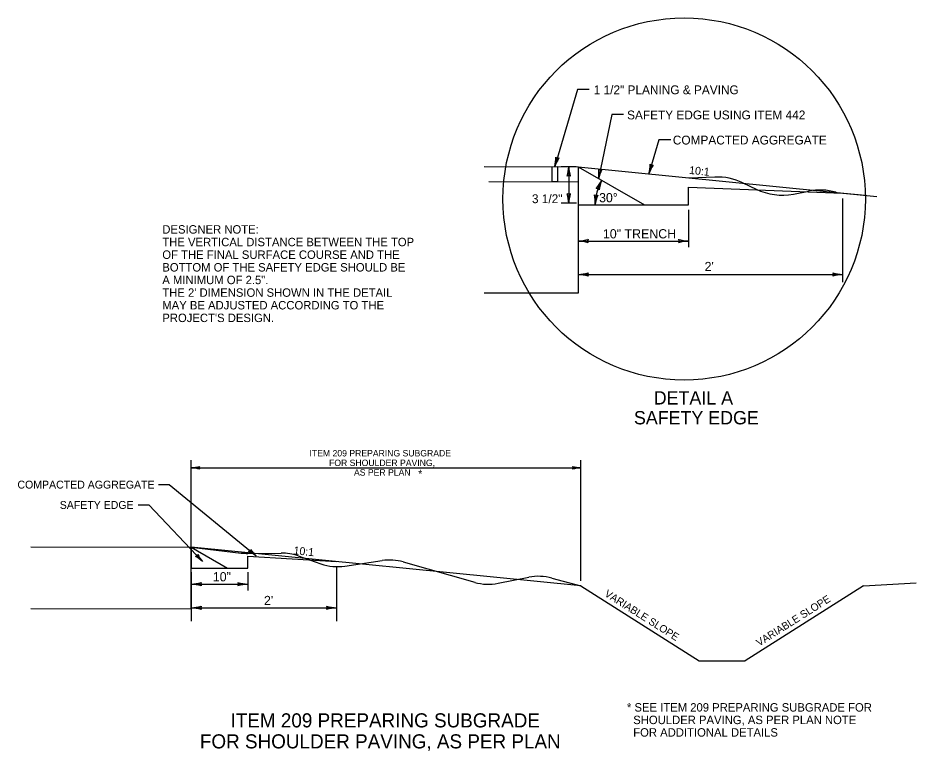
# Model space of a CAD drawing. Extents: x 12069 to 12219, y 28137 to 28231.
# Drawn here: x 12204.37 to 12219.29, y 28184.37 to 28196.55 of the extents above; entities that cross this region are included whole.
import ezdxf

# ---------------------------------------------------------------- set-up
doc = ezdxf.new("R2010")
doc.units = 0
doc.layers.add('Default', color=7, linetype='Continuous')
doc.layers.add('SH_Data', color=7, linetype='Continuous')

msp = doc.modelspace()

# ---------------------------------------------------------------- linework, layer by layer
at = {"layer": 'Default'}
for p, q in [((12213.665, 28195.359), (12213.289, 28194.077)), ((12213.862, 28195.359), (12213.665, 28195.359)), ((12214.236, 28194.941), (12214.017, 28193.874)), ((12214.433, 28194.941), (12214.236, 28194.941)), ((12215.019, 28194.524), (12214.854, 28193.958)), ((12215.217, 28194.524), (12215.019, 28194.524)), ((12213.679, 28194.076), (12213.679, 28193.47)), ((12213.679, 28194.076), (12214.777, 28193.442)), ((12213.679, 28194.076), (12218.639, 28193.578)), ((12213.679, 28193.86), (12213.679, 28193.813)), ((12213.679, 28193.86), (12213.679, 28191.976)), ((12215.519, 28193.891), (12215.95, 28193.905)), ((12216.411, 28193.808), (12216.634, 28193.701)), ((12215.509, 28193.442), (12215.509, 28193.733)), ((12217.252, 28193.622), (12217.506, 28193.67)), ((12213.679, 28193.442), (12214.777, 28193.442)), ((12214.777, 28193.442), (12215.509, 28193.442)), ((12213.679, 28191.976), (12212.119, 28191.976)), ((12206.71, 28188.797), (12206.886, 28188.797)), ((12206.886, 28188.797), (12208.33, 28187.608)), ((12206.371, 28188.459), (12206.547, 28188.459)), ((12206.547, 28188.459), (12207.439, 28187.515)), ((12213.721, 28187.108), (12207.253, 28187.755)), ((12207.253, 28187.755), (12208.083, 28187.656)), ((12208.19, 28187.65), (12208.744, 28187.655)), ((12208.192, 28187.603), (12209.666, 28187.513)), ((12209.027, 28187.609), (12209.406, 28187.476)), ((12209.804, 28187.438), (12210.421, 28187.53)), ((12210.773, 28187.507), (12211.96, 28187.169)), ((12212.35, 28187.153), (12212.859, 28187.254)), ((12213.241, 28187.24), (12213.721, 28187.108))]:
    msp.add_line(p, q, dxfattribs=at)
for points in [[(12217.957, 28193.653), (12217.976, 28193.648), (12218.446, 28193.6)], [(12214.777, 28193.442), (12215.509, 28193.442), (12215.509, 28193.48)]]:
    msp.add_lwpolyline(points, dxfattribs=at)
msp.add_circle((12215.438, 28193.539), 3.009, dxfattribs=at)
for centre, radius, start, end in [((12214.777, 28193.442), 0.817, 150, 180), ((12215.981, 28192.905), 1, 64.5327, 91.7689), ((12217.064, 28194.604), 1, 244.5327, 280.8088), ((12217.693, 28192.688), 1, 74.7222, 100.8088), ((12208.182, 28188.483), 0.833, 263.2067, 270.5549), ((12208.752, 28186.822), 0.833, 70.7156, 90.5549), ((12210.544, 28186.706), 0.833, 74.0884, 98.4697), ((12209.681, 28188.263), 0.833, 250.7156, 278.4697), ((12213.021, 28186.436), 0.833, 74.6316, 101.2096), ((12212.188, 28187.97), 0.833, 254.0884, 281.2096)]:
    msp.add_arc(centre, radius, start, end, dxfattribs=at)
at = {"layer": 'SH_Data'}
for p, q in [((12213.308, 28194.235), (12213.331, 28194.219)), ((12213.331, 28194.219), (12213.359, 28194.22)), ((12214.873, 28194.117), (12214.896, 28194.101)), ((12214.896, 28194.101), (12214.923, 28194.102)), ((12212.119, 28194.078), (12213.679, 28194.076)), ((12213.246, 28194.076), (12213.333, 28194.077)), ((12213.246, 28193.827), (12213.246, 28194.076)), ((12213.333, 28194.077), (12213.333, 28193.826)), ((12213.646, 28194.076), (12213.396, 28194.076)), ((12213.522, 28194.076), (12213.522, 28193.47)), ((12214.02, 28194.034), (12214.044, 28194.021)), ((12214.044, 28194.021), (12214.072, 28194.024)), ((12212.193, 28193.828), (12213.679, 28193.826)), ((12213.333, 28193.826), (12213.246, 28193.827)), ((12213.522, 28193.927), (12213.496, 28193.918)), ((12213.548, 28193.918), (12213.522, 28193.927)), ((12214.005, 28193.709), (12213.976, 28193.712)), ((12214.026, 28193.689), (12214.005, 28193.709)), ((12215.511, 28193.733), (12218.07, 28193.637)), ((12213.522, 28193.618), (12213.496, 28193.627)), ((12213.548, 28193.627), (12213.522, 28193.618)), ((12213.947, 28193.609), (12213.974, 28193.597)), ((12213.974, 28193.597), (12214.002, 28193.604)), ((12218.07, 28193.546), (12218.07, 28192.156)), ((12213.648, 28193.47), (12213.396, 28193.47)), ((12213.679, 28193.388), (12213.679, 28192.337)), ((12215.509, 28193.357), (12215.509, 28192.737)), ((12213.679, 28192.841), (12215.508, 28192.841)), ((12213.844, 28192.869), (12213.835, 28192.841)), ((12213.835, 28192.841), (12213.844, 28192.814)), ((12215.343, 28192.869), (12215.352, 28192.841)), ((12215.352, 28192.841), (12215.343, 28192.814)), ((12213.844, 28192.311), (12213.835, 28192.284)), ((12217.905, 28192.311), (12217.914, 28192.284)), ((12213.679, 28192.284), (12218.07, 28192.284)), ((12213.835, 28192.284), (12213.844, 28192.257)), ((12217.914, 28192.284), (12217.905, 28192.257)), ((12207.253, 28187.828), (12207.253, 28189.197)), ((12213.721, 28187.194), (12213.721, 28189.197)), ((12207.253, 28189.072), (12213.721, 28189.072)), ((12207.386, 28189.072), (12207.394, 28189.095)), ((12207.394, 28189.048), (12207.386, 28189.072)), ((12213.581, 28189.095), (12213.589, 28189.072)), ((12213.589, 28189.072), (12213.581, 28189.048)), ((12207.253, 28187.755), (12207.253, 28187.901)), ((12204.59, 28187.759), (12207.253, 28187.755)), ((12207.253, 28187.755), (12207.857, 28187.406)), ((12207.253, 28187.755), (12207.253, 28187.406)), ((12207.253, 28187.755), (12207.253, 28187.604)), ((12207.253, 28186.731), (12207.253, 28187.755)), ((12208.206, 28187.679), (12208.227, 28187.692)), ((12208.227, 28187.692), (12208.236, 28187.715)), ((12207.326, 28187.601), (12207.348, 28187.611)), ((12207.348, 28187.611), (12207.36, 28187.633)), ((12208.192, 28187.406), (12208.192, 28187.603)), ((12207.253, 28187.406), (12207.857, 28187.406)), ((12207.857, 28187.406), (12208.192, 28187.406)), ((12209.666, 28187.414), (12209.666, 28186.524)), ((12207.253, 28187.338), (12207.253, 28186.524)), ((12208.192, 28187.338), (12208.192, 28187.034)), ((12207.253, 28187.139), (12208.192, 28187.139)), ((12207.418, 28187.166), (12207.409, 28187.139)), ((12207.409, 28187.139), (12207.418, 28187.112)), ((12208.027, 28187.166), (12208.036, 28187.139)), ((12208.036, 28187.139), (12208.027, 28187.112)), ((12213.721, 28187.108), (12215.689, 28185.862)), ((12218.417, 28187.108), (12216.45, 28185.862)), ((12218.417, 28187.108), (12219.289, 28187.161)), ((12204.588, 28186.735), (12207.253, 28186.731)), ((12207.253, 28186.745), (12209.666, 28186.745)), ((12207.418, 28186.772), (12207.409, 28186.745)), ((12207.409, 28186.745), (12207.418, 28186.717)), ((12209.501, 28186.772), (12209.51, 28186.745)), ((12209.51, 28186.745), (12209.501, 28186.717)), ((12215.689, 28185.862), (12216.45, 28185.862))]:
    msp.add_line(p, q, dxfattribs=at)
for centre, radius, start, end in [((12212.568, 28194.244), 0.741, 346.9376, 359.3148), ((12213.987, 28193.828), 0.741, 148.0129, 160.3902), ((12214.132, 28194.126), 0.741, 346.9376, 359.3148), ((12215.551, 28193.71), 0.741, 148.0129, 160.3902), ((12212.782, 28194.118), 0.741, 344.3491, 356.7263), ((12214.261, 28194.118), 0.741, 183.2737, 195.6509), ((12213.282, 28193.97), 0.741, 352.579, 4.9562), ((12214.735, 28193.696), 0.741, 153.6543, 166.0316), ((12213.385, 28194.212), 0.774, 319.8379, 332.2151), ((12214.791, 28193.57), 0.774, 158.7625, 171.1398), ((12212.782, 28193.427), 0.741, 3.2737, 15.6509), ((12214.261, 28193.427), 0.741, 164.3491, 176.7263), ((12213.186, 28193.467), 0.774, 358.1803, 10.5575), ((12214.726, 28193.33), 0.774, 159.2557, 171.6329), ((12213.635, 28193.614), 0.774, 273.2737, 285.6509), ((12213.635, 28192.068), 0.774, 74.3491, 86.7263), ((12215.552, 28193.614), 0.774, 254.3491, 266.7263), ((12215.552, 28192.068), 0.774, 93.2737, 105.6509), ((12213.635, 28193.057), 0.774, 273.2737, 285.6509), ((12218.114, 28193.057), 0.774, 254.3491, 266.7263), ((12213.635, 28191.511), 0.774, 74.3491, 86.7263), ((12218.114, 28191.511), 0.774, 93.2737, 105.6509), ((12207.216, 28189.731), 0.66, 273.2737, 285.6509), ((12207.216, 28188.413), 0.66, 74.3491, 86.7263), ((12213.759, 28189.731), 0.66, 254.3491, 266.7263), ((12213.759, 28188.413), 0.66, 93.2737, 105.6509), ((12207.94, 28187.075), 0.66, 53.7955, 66.1727), ((12208.778, 28188.092), 0.66, 214.8709, 227.2481), ((12206.986, 28187.035), 0.66, 46.642, 59.0193), ((12207.944, 28187.94), 0.66, 207.7174, 220.0946), ((12207.209, 28187.912), 0.774, 273.2737, 285.6509), ((12207.209, 28186.366), 0.774, 74.3491, 86.7263), ((12208.236, 28187.912), 0.774, 254.3491, 266.7263), ((12208.236, 28186.366), 0.774, 93.2737, 105.6509), ((12207.209, 28187.518), 0.774, 273.2737, 285.6509), ((12207.209, 28185.972), 0.774, 74.3491, 86.7263), ((12209.71, 28187.518), 0.774, 254.3491, 266.7263), ((12209.71, 28185.972), 0.774, 93.2737, 105.6509)]:
    msp.add_arc(centre, radius, start, end, dxfattribs=at)

# ---------------------------------------------------------------- texts
at = {"layer": 'Default'}
for p in [(12215.516, 28193.957), (12208.947, 28187.636)]:
    msp.add_text('10:1', height=0.131, rotation=354.2894, dxfattribs=at).set_placement(p)
at = {"layer": 'SH_Data'}
for s, height, p in [('1 1/2" PLANING & PAVING', 0.147, (12213.936, 28195.28)), ('SAFETY EDGE USING ITEM 442', 0.147, (12214.49, 28194.862)), ('COMPACTED AGGREGATE', 0.147, (12215.25, 28194.445)), ('30%%D', 0.1524, (12214.026, 28193.485)), ('3 1/2"', 0.147, (12212.91, 28193.47)), ('DESIGNER NOTE:', 0.14, (12206.772, 28192.964)), ('10" TRENCH', 0.1537, (12214.089, 28192.884)), ('THE VERTICAL DISTANCE BETWEEN THE TOP', 0.14, (12206.772, 28192.754)), ('OF THE FINAL SURFACE COURSE AND THE', 0.14, (12206.772, 28192.544)), ('BOTTOM OF THE SAFETY EDGE SHOULD BE', 0.14, (12206.772, 28192.334)), ("2'", 0.1537, (12215.777, 28192.34)), ('A MINIMUM OF 2.5".', 0.14, (12206.772, 28192.124)), ("THE 2' DIMENSION SHOWN IN THE DETAIL", 0.14, (12206.772, 28191.914)), ('MAY BE ADJUSTED ACCORDING TO THE ', 0.14, (12206.772, 28191.704)), ("PROJECT'S DESIGN.", 0.14, (12206.772, 28191.494)), ('DETAIL A', 0.2215, (12214.933, 28190.124)), ('SAFETY EDGE', 0.22148, (12214.604, 28189.794)), ('ITEM 209 PREPARING SUBGRADE', 0.10716, (12209.217, 28189.261)), ('FOR SHOULDER PAVING,', 0.10716, (12209.541, 28189.101)), ('AS PER PLAN', 0.10716, (12209.955, 28188.942)), ('*', 0.132, (12211.02, 28188.907)), ('COMPACTED AGGREGATE', 0.13098, (12204.366, 28188.727)), ('SAFETY EDGE', 0.13098, (12205.069, 28188.389)), ('10"', 0.1537, (12207.611, 28187.185)), ("2'", 0.1537, (12208.46, 28186.79)), ('* SEE ITEM 209 PREPARING SUBGRADE FOR', 0.14, (12214.488, 28185.021)), ('ITEM 209 PREPARING SUBGRADE', 0.23438, (12207.905, 28184.758)), ('  SHOULDER PAVING, AS PER PLAN NOTE', 0.14, (12214.488, 28184.813)), ('  FOR ADDITIONAL DETAILS', 0.14, (12214.488, 28184.605)), ('FOR SHOULDER PAVING, AS PER PLAN', 0.23438, (12207.396, 28184.409))]:
    msp.add_text(s, height=height, dxfattribs=at).set_placement(p)
for rotation, p in [(327.6541, (12214.104, 28186.949)), (32.3459, (12216.683, 28186.1))]:
    msp.add_text('VARIABLE SLOPE', height=0.12474, rotation=rotation, dxfattribs=at).set_placement(p)

doc.saveas('drawing.dxf')
